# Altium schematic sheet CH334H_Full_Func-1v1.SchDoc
size 322 x 220 mm; PageSetup: Record=PageOptions¦CenterHorizontal=True¦CenterVertical=True¦PrintScale=0.65¦XCorrection=1.00¦YCorrection=1.00¦PrintKind=1¦BorderSize=5000000¦LeftOffset=0¦BottomOffset=0¦Orientation=2¦PaperLength=1000¦PaperWidth=1000¦Scale=100¦PaperSource=7¦PrintQuality=-4¦MediaType=1¦DitherType=10¦PaperKind=16 开 195x270¦PrintScaleMode=1
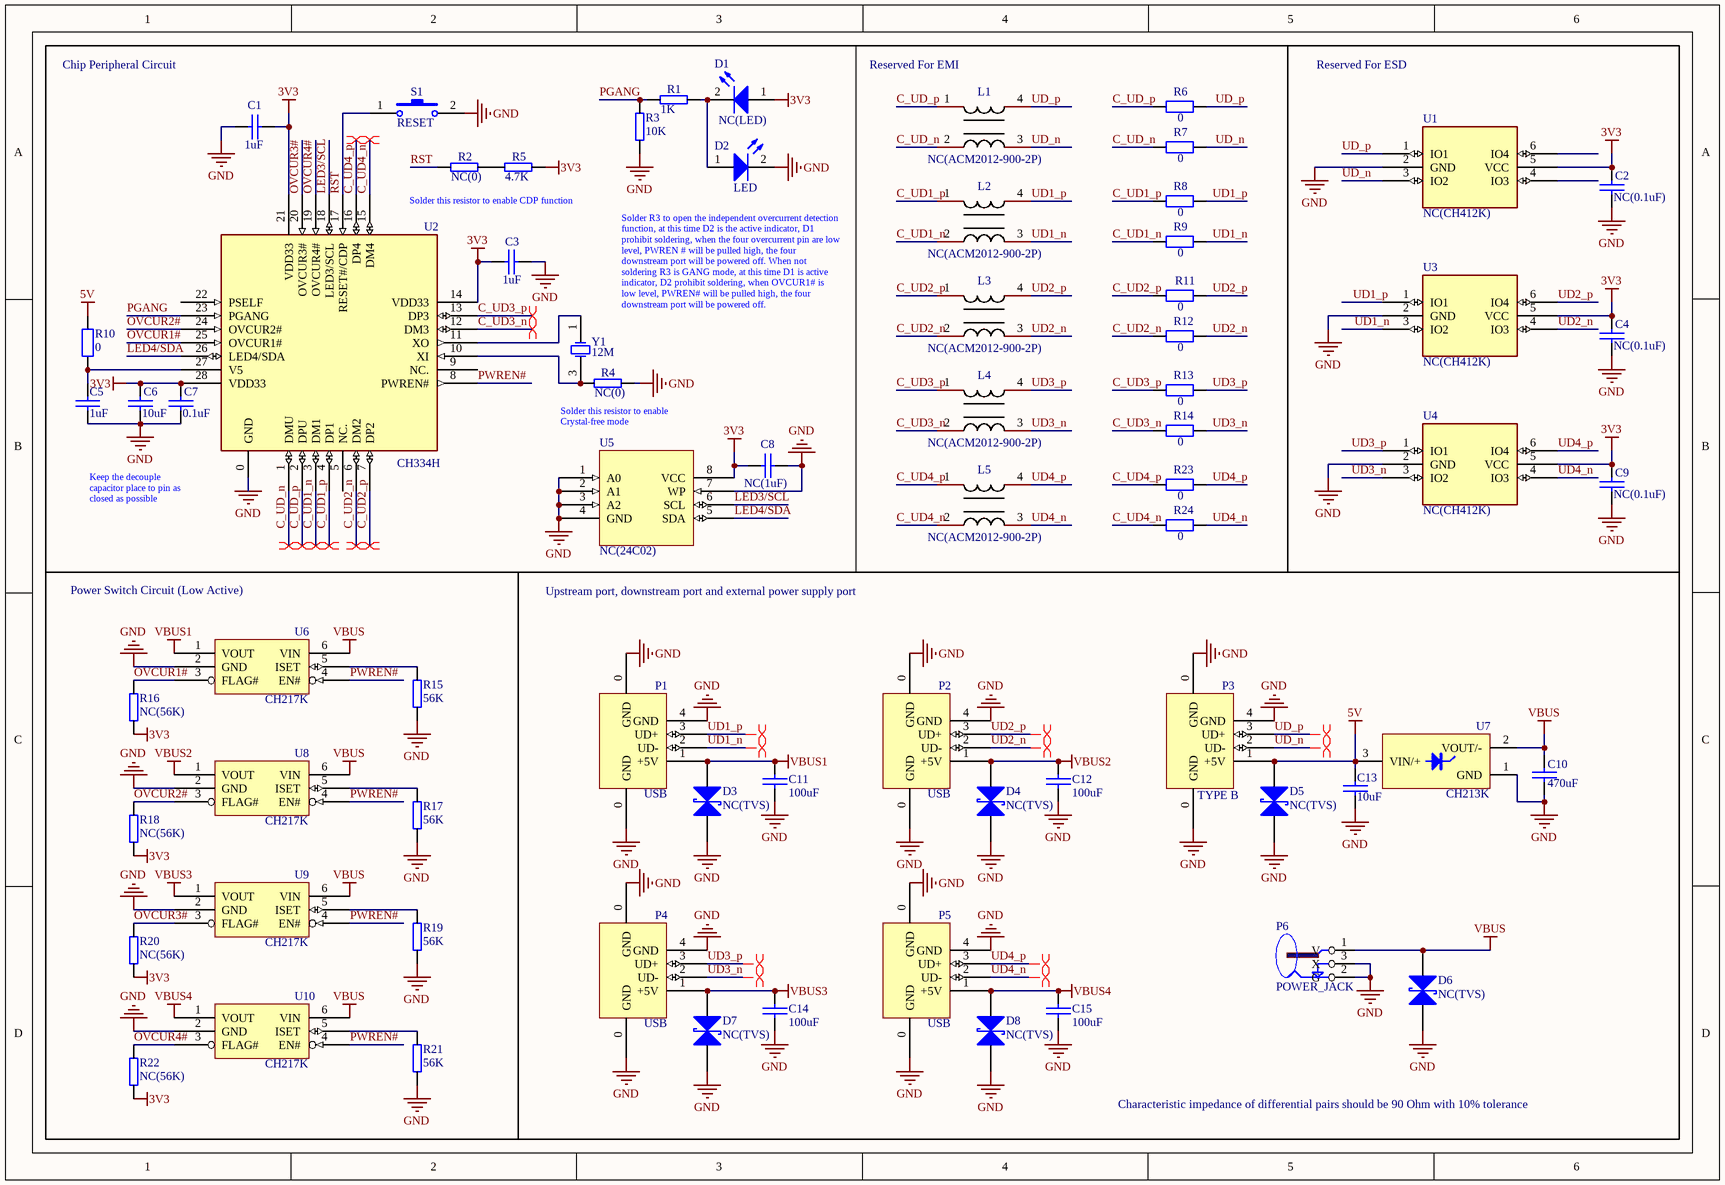
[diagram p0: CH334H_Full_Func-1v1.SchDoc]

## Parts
C1  1uF  [0402_C]
C2  NC(0.1uF)  [0402_C]
C3  1uF  [0402_C]
C4  NC(0.1uF)  [0402_C]
C5  1uF  [0402_C]
C6  10uF  [0603_C]
C7  0.1uF  [0402_C]
C8  NC(1uF)  [0402_C]
C9  NC(0.1uF)  [0402_C]
C10  470uF  [CAP-D8X12L-P3.5]
C11  100uF  [CD0.1]
C12  100uF  [CD0.1]
C13  10uF  [0603_C]
C14  100uF  [CD0.1]
C15  100uF  [CD0.1]
D1  NC(LED)  [0603+]
D2  LED  [0603+]
D3  NC(TVS)  [D0603-BI]
D4  NC(TVS)  [D0603-BI]
D5  NC(TVS)  [D0603-BI]
D6  NC(TVS)  [D0603-BI]
D7  NC(TVS)  [D0603-BI]
D8  NC(TVS)  [D0603-BI]
L1  NC(ACM2012-900-2P)  [IND-SMD_4P-L2.0-W1.2-TL]
L2  NC(ACM2012-900-2P)  [IND-SMD_4P-L2.0-W1.2-TL]
L3  NC(ACM2012-900-2P)  [IND-SMD_4P-L2.0-W1.2-TL]
L4  NC(ACM2012-900-2P)  [IND-SMD_4P-L2.0-W1.2-TL]
L5  NC(ACM2012-900-2P)  [IND-SMD_4P-L2.0-W1.2-TL]
P1  USB  [USBAF]
P2  USB  [USBAF]
P3  TYPE B  [USBB]
P4  USB  [USBAF]
P5  USB  [USBAF]
P6  POWER_JACK  [DC-005]
R1  1K  [0402]
R2  NC(0)  [0402]
R3  10K  [0402]
R4  NC(0)  [0402]
R5  4.7K  [0402]
R6  0  [0603_R]
R7  0  [0603_R]
R8  0  [0603_R]
R9  0  [0603_R]
R10  0  [0402]
R11  0  [0603_R]
R12  0  [0603_R]
R13  0  [0603_R]
R14  0  [0603_R]
R15  56K  [0402]
R16  NC(56K)  [0402]
R17  56K  [0402]
R18  NC(56K)  [0402]
R19  56K  [0402]
R20  NC(56K)  [0402]
R21  56K  [0402]
R22  NC(56K)  [0402]
R23  0  [0603_R]
R24  0  [0603_R]
S1  RESET  [SMD_6.1x3.65x2.5mm-KEY]
U1  NC(CH412K)  [SOT-363]
U2  CH334H  [QFN28_5X5]
U3  NC(CH412K)  [SOT-363]
U4  NC(CH412K)  [SOT-363]
U5  NC(24C02)  [SOIC-8_150mil]
U6  CH217K  [SOT-23-6]
U7  CH213K  [SOT-23-3]
U8  CH217K  [SOT-23-6]
U9  CH217K  [SOT-23-6]
U10  CH217K  [SOT-23-6]
Y1  12M  [XT3225]

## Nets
3V3: C1.1 C2.1 C3.2 C4.1 C6.2 C7.2 C8.1 C9.1 D1.1(A) R5.2 R16.1 R18.1 R20.1 R22.1 U1.5(VCC) U2.14(VDD33) U2.21(VDD33) U2.28(VDD33) U3.5(VCC) U4.5(VCC) U5.8(VCC)
5V: C13.1 D5.2(K) P3.1(+5V) R10.1 U7.3(VIN/+)
GND: C1.2 C2.2 C3.1 C4.2 C5.1 C6.1 C7.1 C8.2 C9.2 C10.2 C11.2 C12.2 C13.2 C14.2 C15.2 D2.2(K) D3.1(A) D4.1(A) D5.1(A) D6.1(A) D7.1(A) D8.1(A) P1.0(GND) P1.4(GND) P2.0(GND) P2.4(GND) P3.0(GND) P3.4(GND) P4.0(GND) P4.4(GND) P5.0(GND) P5.4(GND) P6.2(G) P6.3(X) R3.1 R4.2 R15.1 R17.1 R19.1 R21.1 S1.2 U1.2(GND) U2.0(GND) U3.2(GND) U4.2(GND) U5.1(A0) U5.2(A1) U5.3(A2) U5.4(GND) U5.7(WP) U6.2(GND) U7.1(GND) U8.2(GND) U9.2(GND) U10.2(GND)
VBUS: C10.1 D6.2(K) P6.1(V) U6.6(VIN) U7.2(VOUT/-) U8.6(VIN) U9.6(VIN) U10.6(VIN)
VBUS1: C11.1 D3.2(K) P1.1(+5V) U6.1(VOUT)
VBUS2: C12.1 D4.2(K) P2.1(+5V) U8.1(VOUT)
VBUS3: C14.1 D7.2(K) P4.1(+5V) U9.1(VOUT)
VBUS4: C15.1 D8.2(K) P5.1(+5V) U10.1(VOUT)
C_UD1_n: L2.2 R9.1 U2.3(DM1)
C_UD1_p: L2.1 R8.1 U2.4(DP1)
C_UD2_n: L3.2 R12.1 U2.6(DM2)
C_UD2_p: L3.1 R11.1 U2.7(DP2)
C_UD3_n: L4.2 R14.1 U2.12(DM3)
C_UD3_p: L4.1 R13.1 U2.13(DP3)
C_UD4_n: L5.2 R24.1 U2.15(DM4)
C_UD4_p: L5.1 R23.1 U2.16(DP4)
C_UD_n: L1.2 R7.1 U2.1(DMU)
C_UD_p: L1.1 R6.1 U2.2(DPU)
LED3/SCL: U2.18(LED3/SCL) U5.6(SCL)
LED4/SDA: U2.26(LED4/SDA) U5.5(SDA)
OVCUR1#: R16.2 U2.25(OVCUR1#) U6.3(FLAG#)
OVCUR2#: R18.2 U2.24(OVCUR2#) U8.3(FLAG#)
OVCUR3#: R20.2 U2.20(OVCUR3#) U9.3(FLAG#)
OVCUR4#: R22.2 U2.19(OVCUR4#) U10.3(FLAG#)
PGANG: R1.1 R3.2 U2.23(PGANG)
PWREN#: U2.8(PWREN#) U6.4(EN#) U8.4(EN#) U9.4(EN#) U10.4(EN#)
RST: R2.1 S1.1 U2.17(RESET#/CDP)
UD1_n: L2.3 P1.2(UD-) R9.2 U3.3(IO2)
UD1_p: L2.4 P1.3(UD+) R8.2 U3.1(IO1)
UD2_n: L3.3 P2.2(UD-) R12.2 U3.4(IO3)
UD2_p: L3.4 P2.3(UD+) R11.2 U3.6(IO4)
UD3_n: L4.3 P4.2(UD-) R14.2 U4.3(IO2)
UD3_p: L4.4 P4.3(UD+) R13.2 U4.1(IO1)
UD4_n: L5.3 P5.2(UD-) R24.2 U4.4(IO3)
UD4_p: L5.4 P5.3(UD+) R23.2 U4.6(IO4)
UD_n: L1.3 P3.2(UD-) R7.2 U1.3(IO2)
UD_p: L1.4 P3.3(UD+) R6.2 U1.1(IO1)
NetC5_2: C5.2 R10.2 U2.27(V5)
NetD1_2: D1.2(K) D2.1(A) R1.2
NetR2_2: R2.2 R5.1
NetR4_1: R4.1 U2.10(XI) Y1.3(OSC2)
NetR15_2: R15.2 U6.5(ISET)
NetR17_2: R17.2 U8.5(ISET)
NetR19_2: R19.2 U9.5(ISET)
NetR21_2: R21.2 U10.5(ISET)
NetU2_11: U2.11(XO) Y1.1(OSC1)

Not connected (* = marked no-connect by the designer): U1 4(IO3) 6(IO4); U2 5(NC.) 9(NC.) 22(PSELF)

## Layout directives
differential pair: C_UD1_n, C_UD1_p, C_UD2_n, C_UD2_p, C_UD3_n, C_UD3_p, C_UD4_n, C_UD4_p, C_UD_n, C_UD_p, UD1_n, UD1_p, UD2_n, UD2_p, UD3_n, UD3_p, UD4_n, UD4_p, UD_n, UD_p

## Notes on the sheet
- Chip Peripheral Circuit
- (near L1) Reserved For EMI
- Reserved For ESD
- Solder this resistor to enable CDP function
- Solder R3 to open the independent overcurrent detection function, at this time D2 is the active indicator, D1 prohibit soldering, when the four overcurrent pin are low level, PWREN # will be pulled high, the four downstream port will be powered off. When not soldering R3 is GANG mode, at this time D1 is active indicator, D2 prohibit soldering, when OVCUR1# is low level, PWREN# will be pulled high, the four downstream port will be powered off.
- (near R4) Solder this resistor to enable Crystal-free mode
- Keep the decouple capacitor place to pin as closed as possible
- Power Switch Circuit (Low Active)
- Upstream port, downstream port and external power supply port
- Characteristic impedance of differential pairs should be 90 Ohm with 10% tolerance

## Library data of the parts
C1-C15 = CAP: Capacitor
D1 D2 = LED: Typical INFRARED GaAs LED
D3-D8 = 双向TVS
L1-L5 = ACM2012-900-2P-T002: Manufacturer: TDK; Add into BOM: yes; Number of Lines: 2; Withstanding Voltage: 50V; Current Rating: 400mA; Impedance @ Frequency: 90Ω@100MHz; DC Resistance (DCR): 190mΩ
P1-P5 = USB: USB Port
R1-R5 R15-R22 = RES
R6-R9 R11-R14 R23 R24 = R-High Precision: 贴片精密电阻
R10 = R: 贴片电阻
S1 = SW-PB: Switch
U1 U3 U4 = CH412K: Qaud ESD protect, high speed
U2 = CH334H: 4 ports High-Speed USB MTT Hub with 4 over current detect
U5 = 24C01
U6 U8-U10 = CH217K: Current-Limited USB Power Distribution Switch
U7 = CH213K: Ideal Diode 5V*1A
Y1 = XTAL: Crystal Oscillator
